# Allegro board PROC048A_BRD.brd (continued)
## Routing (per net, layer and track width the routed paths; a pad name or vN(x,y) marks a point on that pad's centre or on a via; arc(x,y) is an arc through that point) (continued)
AR1243_LVDS_MODE: length 53.7
  TOP w0.14: SW2.3 11.4,72.65 11.54,72.79 v1(12.01,72.79) ; U12.C6 v1(39.4,40.31)
  L03_SIG1 w0.107: v1(12.01,72.79) 13.56,71.24 13.56,68.88 23.59,58.85 33.62,58.85 36.7,55.77 36.7,53.35 36.04,52.68 36.04,43.68 v1(39.4,40.31)
  BOTTOM w0.14: v1(12.01,72.79) 11.51,72.79 11.4,72.68 R175.2
BST1_REGA: length 1.8
  TOP w0.457: U1.15 30.29,81.35 30.7,80.95
BST1_REGB: length 1.8
  TOP w0.457: 55.47,80.95 55.06,81.35 U2.15
BST2_REGA: length 1.7
  TOP w0.457: U1.10 27.05,81.43 26.68,81.07
BST2_REGB: length 1.7
  TOP w0.457: 51.45,81.07 51.81,81.43 U2.10
C_RGMII_RXC: length 6.4
  TOP w0.14: R47.2 55.38,58.3 56.23,57.45 57.88,57.45 59,58.57 60.18,58.57 U6.43
C_RGMII_RXCTL: length 9.6
  TOP w0.14: R66.2 59.02,49.45 59.23,49.66 R64.2 59.78,50.08 60.55,49.32 61.69,49.32 62.54,50.17 R63.2 62.54,51.32 64.13,52.91 64.13,54.12
C_RGMII_RXD0: length 7.5
  TOP w0.14: U6.44 59.14,58.07 58.01,56.94 56.99,56.94 v1(56.36,56.31) 56.1,56.05 55.89,56.05 R48.1
  BOTTOM w0.14: v1(56.36,56.31) 56.36,56.43 56.65,56.73 R185.2 R184.2
C_RGMII_RXD1: length 10.5
  TOP w0.14: U6.45 59.27,57.57 56.36,54.66 56.1,54.66 53.56,52.12 52.8,52.12 52.55,51.86 R60.1
C_RGMII_RXD2: length 12
  TOP w0.14: U6.46 60.1,56.99 59.33,56.99 58.9,56.56 58.9,55.04 58.01,54.15 56.48,54.15 v1(54.32,51.99) 54.07,51.99 53.69,51.61 R61.1
  BOTTOM w0.14: R186.1 R187.2 54.83,51.85 54.69,51.99 v1(54.32,51.99)
C_RGMII_RXD3: length 10.9
  TOP w0.14: U6.47 61.17,56.57 61.31,56.43 61.31,54.78 60.04,53.51 56.61,53.51 54.83,51.74 R62.1
C_RGMII_RXD4: length 10.7
  TOP w0.14: v1(59.09,54.09) 59.48,54.09 60.18,54.8 U6.48
  BOTTOM w0.14: R189.1 R188.2 53.69,52.12 54.2,52.62 57.63,52.62 v1(59.09,54.09)
C_RGMII_RXD6: length 9.5
  TOP w0.14: U6.50 62.63,53.15 62.49,53.01 58.77,53.01 57.75,51.99 57.75,50.72 57.63,50.6 R59.2 R65.1
C_RGMII_RXD7: length 6.3
  TOP w0.14: R55.1 R56.2 60.3,52.25 60.67,52.62 62.71,52.62 63.13,53.05 U6.51
CAPTURE_START: length 51.6
  TOP w0.14: C89.2 R153.2 R151.1 v1(2.63,14.2) ; v1(34.38,28.49) 35.58,28.49 U12.U1
  L08_SIG2 w0.107: v1(34.38,28.49) 33.5,27.61 33.5,24.56 31.97,23.03 31.97,19.86 33.43,18.4 33.43,14.84 32.23,13.64 3.2,13.64 v1(2.63,14.2)
CFG0: length 24.9
  TOP w0.14: U12.U4 v1(37.8,28.31) ; v1(28.29,14.27) S1.7
  L03_SIG1 w0.107: v1(37.8,28.31) 37.38,27.9 37.38,26.56 37.16,26.33 36.8,26.33 36.62,26.16 36.62,25.52 36.29,25.19 36.29,21.13 33.88,18.72 33.88,15.16 31.97,13.25 29.3,13.25 v1(28.29,14.27)
  BOTTOM w0.14: v1(28.29,14.27) R217.2
CFG1: length 24.3
  TOP w0.14: v1(29.56,14.27) S1.6 ; U12.T4 v1(37.8,29.11)
  L03_SIG1 w0.107: v1(29.56,14.27) 30.12,13.71 31.79,13.71 33.37,15.29 33.37,18.59 35.81,21.03 35.81,26.97 35.94,27.1 36.47,27.1 36.59,27.22 36.59,28.8 36.91,29.11 v1(37.8,29.11)
  BOTTOM w0.14: R216.2 v1(29.56,14.27)
CFG2: length 22.5
  TOP w0.14: S1.5 v1(30.83,14.14) ; U12.R4 v1(37.8,29.91)
  L03_SIG1 w0.107: v1(30.83,14.14) 30.83,17.95 32.86,19.99 33.11,19.99 35.02,21.89 35.02,26.97 35.65,27.61 35.65,28.37 36.8,29.51 37.4,29.51 v1(37.8,29.91)
  BOTTOM w0.14: R215.2 v1(30.83,14.14)
CONFIG_VIA_HW: length 57.2
  TOP w0.14: SW2.5 8.86,72.68 9,72.82 v1(9.37,72.82) ; U12.A7 v1(40.2,41.91)
  L03_SIG1 w0.107: v1(9.37,72.82) 11.14,74.6 17.62,74.6 31.72,60.5 36.42,60.5 39.04,57.88 39.04,45.34 38.88,45.18 38.88,43.24 v1(40.2,41.91)
  BOTTOM w0.14: v1(9.37,72.82) 9,72.82 8.86,72.68 R177.2
CONN_SPI_CLK: length 6.6
  TOP w0.14: R92.2 R91.2 26.06,34.59 24.35,34.59 23.3,33.54 J3.9
CONN_SPI_CSN: length 10.4
  TOP w0.14: J3.7 23.04,34.04 23.97,34.97 25.49,34.97 26.13,35.61 26.13,38.4 26.51,38.78 R86.2 R85.2
CONN_SPI_MISO: length 5.1
  TOP w0.14: R96.2 R90.2 13.3,33.32 13.59,33.04 J3.12
CONN_SPI_MOSI: length 8.8
  TOP w0.14: R99.2 28.88,35.55 R101.2 26.38,34.46 26.13,34.21 24.73,34.21 23.56,33.04 J3.11
DATA_TRANS_PROG_LED1: length 83.1
  TOP w0.14: LD1.1 v1(3.02,93.65) ; U12.E6 v1(39.4,38.71)
  L03_SIG1 w0.107: v1(3.02,93.65) 2.51,93.14 2.51,69.39 5.17,66.72 13.3,66.72 23.21,56.82 32.86,56.82 34,55.67 34,43.73 34.89,42.85 35.4,42.85 37.43,40.81 37.84,40.81 38.19,40.46 38.19,39.29 38.37,39.11 39,39.11 v1(39.4,38.71)
DDR3_A0: length 48.7
  TOP w0.14: U12.K18 v1(49.8,34.71) ; U11.K3 v1(76.9,39.68) ; U10.K3 v1(64.29,39.68)
  L08_SIG2 w0.107: v1(49.8,34.71) 49.8,34.97 49.38,35.39 49.38,35.73 49.58,35.93 51.93,35.93 52.8,36.81 52.8,37.86 52.37,38.29 51.26,38.29 51.15,38.4 51.15,38.66 51.26,38.77 53.94,38.77 55.22,40.06 58,40.06 58.39,39.67 58.89,39.67 59.28,40.06 59.76,40.06 59.87,40.17 59.87,41.53 59.99,41.66 60.57,41.66 60.67,41.55 60.67,40.17 60.78,40.06 61.75,40.06 61.86,40.17 61.86,40.77 61.97,40.88 62.18,40.88 62.29,40.77 62.29,40.17 62.39,40.06 63.21,40.06 63.59,39.68 v1(64.29,39.68) 64.74,39.68 65.13,40.06 67.41,40.06 67.91,40.56 67.91,41.07 68.5,41.66 73.62,41.66 75.6,39.68 v1(76.9,39.68)
  BOTTOM w0.14: RA6.6 76.67,44.07 75.9,43.3 75.9,40.67 v1(76.9,39.68)
DDR3_A1: length 47.6
  TOP w0.14: U11.L7 v1(72.9,40.48) ; U10.L7 v1(61.09,40.48) ; U12.G20 v1(53.17,36.71)
  L03_SIG1 w0.107: v1(53.17,36.71) 52.87,36.71 52.77,36.82 52.77,36.97 53.94,38.15 53.94,38.79 53.84,38.89 53.03,38.89 52.93,39 52.93,39.21 53.03,39.32 53.84,39.32 53.94,39.43 53.94,40.31 54.07,40.43 55.72,40.43 55.97,40.69 55.97,42.85 56.48,43.35 56.48,45.13 57.22,45.87 59.81,45.87 59.91,45.77 59.91,43.86 59.66,43.61 59.02,43.61 58.64,43.23 58.64,41.07 58.85,40.86 60.49,40.86 60.53,40.81 60.75,40.81 v1(61.09,40.48) 62.51,40.48 63.73,41.7 66.89,41.7 67.39,42.2 69.29,42.2 69.4,42.09 69.4,40.72 69.69,40.43 70.71,40.43 71.13,40.86 72.52,40.86 v1(72.9,40.48)
  BOTTOM w0.14: RA7.7 73.5,43.4 73.78,43.13 73.78,41.04 73.22,40.48 v1(72.9,40.48)
DDR3_A2: length 47.8
  TOP w0.14: v1(52.01,37.11) 50.6,37.11 U12.G19 ; U11.L3 v1(76.9,40.48) ; U10.L3 v1(64.29,40.48)
  L08_SIG2 w0.107: v1(52.01,37.11) 49.54,37.11 48.99,37.66 48.99,37.99 49.33,38.33 50.15,38.33 50.26,38.44 50.26,39.26 50.42,39.42 53.51,39.42 54.07,39.98 54.07,40.81 54.26,41 55.54,41 55.83,40.7 58.02,40.7 58.64,41.32 58.64,42.34 59.28,42.97 61.82,42.97 61.94,42.85 61.94,42.59 62.07,42.46 62.35,42.46 62.45,42.57 62.45,42.87 62.56,42.97 62.87,42.97 63.02,42.82 63.02,41.18 63.72,40.48 v1(64.29,40.48) 64.6,40.48 65.02,40.9 66.05,40.9 67.93,42.78 74,42.78 76.31,40.48 v1(76.9,40.48)
  BOTTOM w0.14: v1(76.9,40.48) 76.32,41.06 76.32,43.13 77.17,43.98 RA6.5
DDR3_A3: length 47.5
  TOP w0.14: U11.K2 v1(77.7,39.68) ; U12.J18 v1(49.8,35.51) ; U10.K2 v1(65.89,39.68)
  L08_SIG2 w0.107: v1(77.7,39.68) 77.32,39.3 75.53,39.3 73.96,40.86 70.96,40.86 70.5,41.32 68.8,41.32 68.42,40.94 68.42,39.67 68.04,39.29 66.52,39.29 66.13,39.68 v1(65.89,39.68) 65.25,39.68 64.83,39.26 61.66,39.26 61.31,38.91 60.04,38.91 59.66,39.29 58.2,39.29 57.82,39.67 56.61,39.67 56.48,39.54 56.48,38.53 56.36,38.4 56.1,38.4 55.97,38.53 55.97,39.54 55.85,39.67 55.34,39.67 55.09,39.42 55.09,38.65 54.83,38.4 53.69,38.4 53.56,38.27 53.56,36.5 53.33,36.27 52.95,36.27 52.2,35.51 51.73,35.51 51.62,35.41 51.62,34.32 51.52,34.21 51.3,34.21 51.2,34.32 51.2,35.41 51.09,35.51 50.88,35.51 50.77,35.41 50.77,34.32 50.66,34.21 50.45,34.21 50.34,34.32 50.34,35.41 50.24,35.51 v1(49.8,35.51)
  BOTTOM w0.14: v1(77.7,39.68) 80.99,39.68 81.16,39.5 81.99,39.5 RA9.8
DDR3_A4: length 48
  TOP w0.14: U10.L8 v1(60.29,40.48) ; U12.J19 50.6,35.51 v1(53.69,35.51) ; U11.L8 v1(72.1,40.48)
  L03_SIG1 w0.107: v1(72.1,40.48) 72.05,40.43 71.85,40.43 71.51,40.1 69.52,40.1 69.06,40.56 69.06,41.7 68.93,41.83 67.79,41.83 67.66,41.7 67.66,41.27 67.25,40.86 63.51,40.86 62.75,40.1 60.93,40.1 60.55,40.48 v1(60.29,40.48) 60.05,40.48 59.63,40.06 58.64,40.06 58.26,40.43 58.26,43.86 58.39,43.99 59.4,43.99 59.53,44.12 59.53,45.39 59.4,45.51 57.37,45.51 56.86,45 56.86,43.1 56.36,42.59 56.36,41.58 56.86,41.07 56.86,40.81 56.1,40.05 54.45,40.05 54.32,39.92 54.32,38.02 53.69,37.38 v1(53.69,35.51)
  BOTTOM w0.14: v1(72.1,40.48) 72.49,40.88 73.06,40.88 73.36,41.18 73.36,42.95 73,43.31 RA7.8
DDR3_A5: length 48.6
  TOP w0.14: U10.L2 v1(65.89,40.48) ; U11.L2 v1(77.7,40.48) ; U12.J16 v1(48.2,35.51)
  L08_SIG2 w0.107: v1(77.7,40.48) 77.32,40.1 75.74,40.1 75.02,40.81 75.02,41.31 73.87,42.46 68.06,42.46 67.66,42.06 67.66,41.29 67.23,40.86 66.46,40.86 66.26,40.66 66.26,40.56 66.18,40.48 v1(65.89,40.48) 65.09,40.48 64.71,40.1 63.65,40.1 62.51,41.23 62.51,41.39 61.31,42.59 59.46,42.59 59.02,42.15 59.02,40.94 58.46,40.38 55.03,40.38 53.75,39.1 50.96,39.1 50.83,38.98 50.83,37.64 50.97,37.51 52.29,37.51 52.42,37.38 52.42,36.88 52.24,36.69 48.84,36.69 48.2,36.05 v1(48.2,35.51)
  BOTTOM w0.14: v1(77.7,40.48) 78.44,41.22 78.71,41.22 79.84,42.36 RA5.5
DDR3_A6: length 47.1
  TOP w0.14: v1(53.05,38.15) 53.69,38.15 53.82,38.27 53.82,38.9 53.68,39.04 52.42,39.04 51.69,38.31 51.01,38.31 U12.E20 ; U10.M8 v1(60.29,41.28) ; U11.M8 v1(72.1,41.28)
  L03_SIG1 w0.107: v1(72.1,41.28) 72.05,41.32 71.86,41.32 71.53,41.66 71.04,41.66 70.71,41.32 69.94,41.32 69.82,41.45 69.82,42.34 69.64,42.52 63.14,42.52 62.83,42.21 62.83,41.32 62.41,40.9 61.48,40.9 61.24,41.13 60.66,41.13 60.52,41.28 v1(60.29,41.28) 60.03,41.28 59.64,41.66 59.13,41.66 59.02,41.77 59.02,42.85 59.28,43.1 59.91,43.1 60.29,43.48 60.29,43.86 60.29,46.07 60.17,46.2 56.91,46.2 56.1,45.39 56.1,43.73 55.59,43.23 55.59,41.19 55.21,40.81 53.05,40.81 52.55,40.31 52.55,37.62 52.65,37.52 52.8,37.52 53.05,37.77 v1(53.05,38.15)
  BOTTOM w0.14: v1(72.1,41.28) 71.69,41.68 71.69,42.24 70.34,43.6 RA8.8
DDR3_A7: length 47.8
  TOP w0.14: U12.K17 v1(49,34.71) ; U10.M2 v1(65.89,41.28) ; U11.M2 v1(77.7,41.28)
  L08_SIG2 w0.107: v1(77.7,41.28) 77.7,41 77.51,40.81 77.18,40.81 77.14,40.86 76.37,40.86 75.91,41.32 75.91,41.7 74.52,43.1 67.02,43.1 66.26,42.34 66.26,41.65 v1(65.89,41.28) 64.95,41.28 64.57,40.9 63.76,40.9 63.34,41.31 63.34,42.95 63,43.29 58.96,43.29 58.26,42.59 58.26,41.7 57.68,41.13 55.92,41.13 55.72,41.32 54.07,41.32 53.69,40.94 53.69,40.05 53.43,39.8 50.35,39.8 48.48,37.93 48.48,36.79 47.82,36.12 47.82,35.36 48.04,35.13 48.35,35.13 48.77,34.71 v1(49,34.71)
  BOTTOM w0.14: RA5.6 79.34,42.36 78.56,41.58 78,41.58 v1(77.7,41.28)
DDR3_A8: length 46.2
  TOP w0.14: U11.N8 v1(72.1,42.08) ; U10.N8 v1(60.29,42.08) ; U12.J20 v1(52.8,35.11)
  L03_SIG1 w0.107: v1(72.1,42.08) 72.74,42.72 72.74,43.13 72.63,43.23 62.84,43.23 61.43,41.82 60.93,41.82 60.67,42.08 v1(60.29,42.08) 60.29,42.46 61.05,43.23 61.05,46.45 60.67,46.84 55.8,46.84 55.28,46.32 55.28,43.98 52.88,41.58 52.87,41.58 51.47,40.17 51.47,36.18 51.78,35.86 53.18,35.86 53.31,35.73 53.31,35.22 53.2,35.11 v1(52.8,35.11)
  BOTTOM w0.14: v1(72.1,42.08) 72.1,42.44 70.84,43.7 RA8.7
DDR3_A9: length 47.5
  TOP w0.14: U10.M3 v1(64.29,41.28) ; U11.M3 v1(76.9,41.28) ; U12.D20 51.35,39.11 52.93,40.69 52.93,41.71 53.17,41.96 53.69,41.96 53.88,41.77 53.88,40.43 53.76,40.31 v1(53.31,40.31)
  L08_SIG2 w0.107: v1(53.31,40.31) 52.27,40.31 52.16,40.41 52.16,41.22 52.27,41.32 53.46,41.32 53.79,41.64 55.03,41.64 55.16,41.78 55.16,42.87 55.27,42.97 55.87,42.97 55.97,42.87 55.97,41.58 56.1,41.45 57.5,41.45 57.88,41.83 57.88,43.61 58.19,43.92 62.83,43.92 63.66,43.09 63.66,41.45 63.83,41.28 v1(64.29,41.28) 64.61,41.6 65.2,41.6 65.72,42.12 65.72,42.3 66.9,43.48 74.7,43.48 v1(76.9,41.28)
  BOTTOM w0.14: v1(76.9,41.28) 77.3,41.68 77.3,42.33 78.84,43.87 RA5.7
DDR3_A10: length 51.1
  TOP w0.14: U12.K19 50.6,34.71 53.56,34.71 54.2,35.35 54.2,36.36 54.34,36.5 55.09,36.5 55.34,36.24 55.34,34.72 55.12,34.5 54.79,34.5 v1(54.45,34.84) ; U11.H7 v1(72.9,38.08) ; U10.H7 v1(61.89,37.28)
  L03_SIG1 w0.107: v1(54.45,34.84) 54.45,35.61 54.58,35.73 54.78,35.73 54.96,35.55 54.96,34.02 55.07,33.91 55.23,33.91 55.34,34.02 55.34,35.25 55.45,35.35 56.25,35.35 56.36,35.25 56.36,34.32 56.46,34.21 57.75,34.21 58.51,34.97 58.51,37.51 58.7,37.7 60.49,37.7 60.8,37.38 61.18,37.38 61.56,37.77 61.56,38.29 61.67,38.4 62.35,38.4 62.45,38.29 62.45,37.84 v1(61.89,37.28) 61.91,37.26 62.83,37.26 62.96,37.38 62.96,37.79 63.07,37.89 63.36,37.89 63.47,37.79 63.47,37.49 63.57,37.38 64.48,37.38 64.8,37.7 69.9,37.7 70.01,37.59 70.01,37.11 70.12,37 70.33,37 70.44,37.11 70.44,37.59 70.54,37.7 71.28,37.7 71.47,37.51 71.47,37.26 71.85,36.88 72.36,36.88 72.52,37.04 72.52,37.7 v1(72.9,38.08)
  BOTTOM w0.14: v1(72.9,38.08) 73.27,38.45 73.49,38.45 73.57,38.53 74.14,38.53 75.06,39.46 75.06,43.66 75.67,44.27 RA6.8
DDR3_A11: length 47.1
  TOP w0.14: v1(52.01,37.91) 50.6,37.91 U12.F19 ; U10.M7 61.89,41.28 v1(61.98,41.28) ; U11.M7 v1(72.9,41.28)
  L03_SIG1 w0.107: v1(52.01,37.91) 52.01,37.93 51.79,38.14 51.79,38.53 52.23,38.97 52.23,39.36 51.79,39.79 51.79,40.04 52.94,41.19 54.09,41.19 54.2,41.3 54.2,42.23 54.31,42.34 54.52,42.34 54.63,42.23 54.63,41.3 54.73,41.19 54.96,41.19 55.21,41.45 55.21,43.35 55.72,43.86 55.72,45.51 56.73,46.52 60.43,46.52 60.66,46.29 60.66,43.34 59.87,42.55 59.87,41.96 60.13,41.7 60.55,41.7 60.8,41.45 61.8,41.45 v1(61.98,41.28) 62.43,41.73 62.43,42.31 62.95,42.84 63.01,42.84 63.01,42.84 70.09,42.84 70.2,42.73 70.2,42.11 70.33,41.98 70.73,41.98 70.83,42.09 70.83,42.74 70.94,42.85 71.61,42.85 71.72,42.74 71.72,41.92 71.98,41.66 72.52,41.66 v1(72.9,41.28)
  BOTTOM w0.14: RA8.6 71.34,43.79 72.49,42.63 72.49,41.68 v1(72.9,41.28)
DDR3_A12: length 48.9
  TOP w0.14: U12.F20 51.01,37.51 54.45,37.51 v1(54.45,37.51) ; U10.K7 v1(61.09,39.68) ; U11.K7 v1(72.9,39.68)
  L03_SIG1 w0.107: v1(54.45,37.51) 54.45,36.67 54.56,36.56 54.85,36.56 54.96,36.67 54.96,39.54 55.14,39.73 56.29,39.73 57.24,40.69 57.24,41.19 56.74,41.7 56.74,42.34 57.19,42.79 57.19,44.87 57.45,45.13 59.1,45.13 59.21,45.03 59.21,44.48 59.1,44.37 58.01,44.37 57.88,44.24 57.88,40.31 58.89,39.3 59.64,39.3 59.91,39.56 59.91,39.84 60.13,40.06 60.49,40.06 60.77,39.77 60.99,39.77 v1(61.09,39.68) 63.35,39.68 63.73,40.06 66.9,40.06 67.28,40.43 67.68,40.43 67.79,40.54 67.79,40.94 67.91,41.07 68.55,41.07 68.67,40.94 68.67,40.18 69.56,39.3 71.46,39.3 71.68,39.52 71.68,39.8 71.94,40.06 72.52,40.06 v1(72.9,39.68)
  BOTTOM w0.14: v1(72.9,39.68) 73.42,39.68 74.5,40.77 RA7.5
DDR3_A13: length 46.3
  TOP w0.14: U12.L19 50.6,33.91 55.17,33.91 55.34,34.08 57.75,34.08 58.17,34.5 58.17,37.55 57.24,38.47 v1(57.24,41.96) ; U11.N3 v1(76.9,42.08) ; U10.N3 v1(64.29,42.08)
  L08_SIG2 w0.107: v1(57.24,41.96) 56.74,42.46 56.74,43.86 57.12,44.24 62.96,44.24 63.98,43.22 63.98,42.38 v1(64.29,42.08) 64.71,42.5 64.71,43.32 65.25,43.86 75.11,43.86 v1(76.9,42.08)
  BOTTOM w0.14: v1(76.9,42.08) 76.9,42.57 78.34,44.01 RA5.8
DDR3_A14: length 46.3
  TOP w0.14: U11.N7 v1(72.9,42.08) ; U12.K16 v1(48.2,34.71) ; v1(61.09,42.2) 61.09,42.08 U10.N7
  L03_SIG1 w0.107: v1(48.2,34.71) 48.2,34.97 48.58,35.36 48.58,36.47 48.85,36.73 49.23,36.73 49.51,37.01 50.78,37.01 51.11,37.35 51.11,40.27 54.96,44.12 54.96,46.46 55.67,47.16 60.8,47.16 61.44,46.53 61.44,43.1 61.09,42.75 v1(61.09,42.2) 61.36,42.2 62.71,43.55 63.41,43.55 63.42,43.56 73.04,43.56 73.5,43.1 73.5,42.68 v1(72.9,42.08)
  BOTTOM w0.14: v1(72.9,42.08) 72.88,42.09 72.88,42.26 72.91,42.29 72.91,42.81 71.84,43.88 RA8.5
DDR3_A15: length 51.5
  TOP w0.14: U10.J7 v1(61.89,38.88) ; U12.J17 v1(49,35.51) ; U11.J7 v1(73.7,38.08)
  L03_SIG1 w0.107: v1(73.7,38.08) 73.75,38.13 73.75,38.37 73.65,38.47 71.92,38.47 71.47,38.02 68.15,38.02 68.04,38.13 68.04,38.87 67.88,39.04 67.4,39.04 67.28,38.91 67.28,38.13 67.17,38.02 66.52,38.02 66.07,38.47 64.8,38.47 64.39,38.88 v1(61.89,38.88) 60.52,38.88 59.81,38.18 58.29,38.18 58.13,38.02 58.13,35.1 58.01,34.97 57.63,34.97 57.5,35.1 57.5,39.31 57.39,39.42 56.99,39.42 56.48,38.91 56.48,36.24 55.97,35.73 55.47,35.73 55.01,36.19 54.15,36.19 54.07,36.11 54.07,35.05 53.73,34.72 52.29,34.72 51.15,35.86 51.15,36.5 50.95,36.69 49.64,36.69 49.38,36.44 49.38,36.13 49,35.75 v1(49,35.51)
  BOTTOM w0.14: v1(73.7,38.08) 74.94,38.08 75.48,38.62 75.48,43.47 76.17,44.16 RA6.7
DDR3_BA0: length 48.3
  TOP w0.14: U11.J2 v1(77.7,38.88) ; U10.J2 v1(65.89,38.88) ; v1(56.99,37.64) 56.99,38.13 56.85,38.27 55.35,38.27 55.08,38.54 55.08,39.66 55.22,39.8 56.18,39.8 56.32,39.94 56.32,40.89 56.18,41.03 55.57,41.03 55.43,41.17 55.43,41.45 55.57,41.59 56.18,41.59 56.32,41.73 56.32,43.01 56.1,43.23 55.59,43.23 55.47,43.1 55.47,42.59 55.21,42.34 53.05,42.34 52.53,41.81 52.53,40.85 51.2,39.52 50.6,39.52 U12.D19
  L08_SIG2 w0.107: v1(77.7,38.88) 77.28,38.46 75.02,38.46 74.7,38.78 72.96,38.78 72.48,39.26 70.74,39.26 70.58,39.42 70.58,39.95 70.47,40.05 69.29,40.05 69.18,39.95 69.18,39.16 68.2,38.18 66.52,38.18 65.89,38.81 v1(65.89,38.88) 65.85,38.88 65.47,38.5 62.8,38.5 61.96,37.66 57.65,37.66 57.63,37.64 v1(56.99,37.64)
  BOTTOM w0.14: v1(77.7,38.88) 78.87,38.88 79.47,38.27 80.87,38.27 81.1,38.5 81.1,38.5 81.63,39.03 RA9.7
DDR3_BA1: length 49.7
  TOP w0.14: v1(55.53,38.97) 56.17,38.97 56.74,39.54 56.74,43.61 56.48,43.86 55.18,43.86 55.04,43.72 55.04,42.9 54.9,42.76 54.62,42.76 54.48,42.9 54.48,43.72 54.35,43.86 54.07,43.86 53.93,43.72 53.93,42.9 53.79,42.76 52.84,42.76 52.16,42.08 52.16,41.07 U12.C20 ; U11.K8 v1(72.1,39.68) ; U10.K8 v1(60.29,39.68)
  L03_SIG1 w0.107: v1(55.53,38.97) 55.53,36.35 55.64,36.24 55.97,36.24 56.1,36.37 56.1,39.04 56.81,39.74 57.94,39.74 59.18,38.5 59.64,38.5 60.29,39.14 v1(60.29,39.68) 60.67,39.3 67.16,39.3 67.4,39.54 67.4,39.95 67.51,40.05 68.29,40.05 68.42,39.93 68.42,38.91 68.83,38.5 71.46,38.5 71.72,38.76 71.72,39.04 72.1,39.42 v1(72.1,39.68)
  BOTTOM w0.14: RA7.6 74,43.49 74.15,43.35 74.15,40.91 73.31,40.08 72.49,40.08 v1(72.1,39.68)
DDR3_BA2: length 49
  TOP w0.14: U10.J3 v1(65.09,38.88) ; U12.H17 v1(49,36.31) ; U11.J3 v1(76.9,38.88)
  L08_SIG2 w0.107: v1(76.9,38.88) 75.44,38.88 74.26,40.06 71.08,40.06 70.45,40.69 69.18,40.69 68.8,40.31 68.8,39.42 67.88,38.5 66.66,38.5 66.39,38.76 66.39,38.96 66.09,39.26 65.47,39.26 v1(65.09,38.88) 62.55,38.88 62.13,38.46 60.1,38.46 59.71,38.07 57.63,38.07 57.5,38.2 57.5,39.29 57.44,39.35 57.03,39.35 56.93,39.24 56.93,38.18 56.74,37.99 54.22,37.99 53.94,37.72 53.94,36.32 53.57,35.95 53.09,35.95 52.42,35.27 52.42,33.83 52.29,33.7 48.48,33.7 48.37,33.82 48.37,34.09 48.48,34.21 49.24,34.21 49.42,34.39 49.42,34.83 49.12,35.13 48.84,35.13 48.62,35.36 48.62,35.93 v1(49,36.31)
  BOTTOM w0.14: RA9.6 81.72,38.53 81.04,37.85 79.25,37.85 78.63,38.48 77.3,38.48 v1(76.9,38.88)
DDR3_CASN: length 48.7
  TOP w0.14: U11.G3 v1(76.9,37.28) ; U10.G3 v1(65.09,37.28) ; U12.E19 50.6,38.72 51.46,38.72 52.16,39.42 53.43,39.42 54.32,40.31 54.32,41.56 54.46,41.7 54.83,41.7 54.96,41.58 54.96,40.18 54.45,39.67 54.45,38.36 55.62,37.19 57.57,37.19 57.75,37 57.75,35.86 57.63,35.73 v1(56.61,35.73)
  L08_SIG2 w0.107: v1(76.9,37.28) 76.9,36.98 76.79,36.88 71.47,36.88 71.34,37 71.34,37.53 71.24,37.64 70.56,37.64 70.45,37.53 70.45,36.62 70.33,36.5 68.15,36.5 68.04,36.6 68.04,37 67.91,37.13 66.52,37.13 66.26,36.88 65.49,36.88 v1(65.09,37.28) 64.63,37.28 63.21,35.86 63.21,35.61 62.07,34.46 59.02,34.46 58.77,34.21 57.45,34.21 56.61,35.05 v1(56.61,35.73)
  BOTTOM w0.14: RA10.7 81.34,36.36 81.21,36.5 77.82,36.5 77.31,37 77.18,37 76.91,37.28 v1(76.9,37.28)
DDR3_CK: length 45.3
  TOP w0.102: U11.F7 v1(72.9,35.68) ; U12.U18 v1(49.8,28.31) ; U10.F7 v1(61.09,35.68)
  L03_SIG1 w0.089: v1(61.09,35.68) 61.36,35.95 62.92,35.95 63.21,36.24 65.05,36.24 65.48,35.81 68.3,35.81 68.39,35.72 68.39,35.1 68.65,34.84 69.07,34.84 69.33,35.1 69.33,35.72 69.42,35.81 71.45,35.81 71.84,36.2 72.61,36.2 72.73,36.33 72.81,36.33 72.9,36.24 v1(72.9,35.68)
  BOTTOM w0.102: v1(61.09,35.68) 61.09,35.33 61.19,35.23 61.44,35.23 61.56,35.35 61.56,36.1 61.66,36.2 62.48,36.2 62.93,35.75 62.93,30.64 60.79,28.49 58.26,28.49 57.75,29 57.75,30.77 57.49,31.03 56.49,31.03 56.22,30.77 56.22,29.1 56.12,29 52.66,29 51.87,28.22 50.39,28.22 50.26,28.34 50.26,28.58 50.16,28.68 49.9,28.68 49.8,28.58 v1(49.8,28.31) ; R210.1 73.62,36.34 73,36.34 72.9,36.24 v1(72.9,35.68)
DDR3_CKE: length 52.7
  TOP w0.14: U12.L20 51.07,33.45 52.03,33.45 52.17,33.31 52.17,32.32 52.31,32.18 52.59,32.18 52.73,32.32 52.73,33.28 52.87,33.42 53.15,33.42 53.29,33.28 53.29,32.32 53.43,32.18 53.71,32.18 53.85,32.32 53.85,33.28 53.99,33.42 54.48,33.42 54.65,33.25 54.65,31.95 54.79,31.81 55.07,31.81 55.21,31.95 55.21,32.93 55.35,33.07 56.99,33.07 57.24,32.81 58.76,32.81 58.9,32.95 58.9,33.44 58.76,33.57 v1(55.72,33.57) ; v1(70.96,36.62) 71.21,36.88 U11.G9 ; U10.G9 v1(59.49,37.28)
  L03_SIG1 w0.107: v1(55.72,33.57) 55.97,33.83 57.88,33.83 58.9,34.84 58.9,36.01 59,36.11 60.06,36.11 60.17,36.22 60.17,36.39 60.06,36.5 59.11,36.5 58.9,36.71 58.9,37.17 59,37.28 v1(59.49,37.28) 59.87,36.9 66.15,36.9 66.52,37.26 67.53,37.26 67.66,37.13 67.66,36.62 67.79,36.5 68.06,36.5 68.17,36.6 68.17,37.02 68.27,37.13 68.57,37.13 68.67,37.02 68.67,36.6 68.78,36.5 69.06,36.5 69.18,36.62 69.18,37 69.31,37.13 69.56,37.13 69.69,37 69.69,36.75 69.82,36.62 v1(70.96,36.62)
  BOTTOM w0.14: v1(70.96,36.62) 69.82,36.62 69.18,37.26 R191.1
DDR3_CKN: length 45.4
  TOP w0.102: U10.G7 v1(61.09,36.48) ; U12.U17 v1(49,28.31) ; U11.G7 v1(72.9,37.28)
  L03_SIG1 w0.089: v1(72.9,37.28) 72.9,36.71 72.81,36.62 72.61,36.62 72.48,36.5 71.72,36.5 71.33,36.11 69.3,36.11 69.04,35.85 69.04,35.23 68.95,35.14 68.77,35.14 68.68,35.23 68.68,35.85 68.42,36.11 65.6,36.11 65.17,36.53 63.09,36.53 62.8,36.24 61.32,36.24 v1(61.09,36.48)
  BOTTOM w0.102: v1(72.9,37.28) 72.9,36.72 73,36.62 73.58,36.62 R209.1 ; v1(61.09,36.48) 62.6,36.48 63.21,35.86 63.21,30.53 60.9,28.22 58.15,28.22 57.47,28.89 57.47,30.65 57.37,30.76 56.6,30.76 56.5,30.65 56.5,28.99 56.23,28.72 52.77,28.72 51.99,27.94 49.38,27.94 v1(49,28.31)
DDR3_CSN: length 48.2
  TOP w0.14: U12.T17 v1(49,29.11) ; U10.H2 v1(65.89,38.08) ; U11.H2 v1(77.7,38.08)
  L08_SIG2 w0.107: v1(77.7,38.08) 77.32,37.7 75.28,37.7 74.52,38.46 70.14,38.46 70.04,38.57 70.04,39.44 69.93,39.54 69.72,39.54 69.61,39.44 69.61,38.57 69.5,38.46 69.04,38.46 68.42,37.84 66.41,37.84 66.17,38.08 v1(65.89,38.08) 65.82,38.15 62.96,38.15 62.45,37.64 62.45,36.24 62.32,36.11 61.94,36.11 61.82,36.24 61.82,36.75 61.67,36.9 56.59,36.9 56.48,37 56.48,37.53 56.38,37.64 55.95,37.64 55.85,37.53 55.85,36.86 55.74,36.75 55.21,36.75 54.45,35.99 54.45,35.61 53.82,34.97 53.43,34.97 52.8,34.34 52.8,33.19 52.3,32.7 48.84,32.7 48.62,32.47 48.62,29.5 v1(49,29.11)
  BOTTOM w0.14: RA9.5 81.81,38.03 81.22,37.44 81.17,37.44 81.16,37.42 78.35,37.42 v1(77.7,38.08)
DDR3_DM0: length 36.6
  TOP w0.14: U12.U19 50.6,28.31 52.22,28.31 52.42,28.11 52.42,26.08 52.67,25.83 54.2,25.83 54.58,26.21 v1(54.58,28.24) ; U11.B7 v1(72.9,32.48)
  L08_SIG2 w0.107: v1(54.58,28.24) 55.09,28.75 57.88,28.75 58.39,29.26 58.88,29.26 58.99,29.15 58.99,28.24 59.1,28.14 59.31,28.14 59.42,28.24 59.42,29.15 59.52,29.26 59.74,29.26 59.84,29.15 59.84,28.24 59.95,28.14 60.16,28.14 60.27,28.24 60.27,29.15 60.38,29.26 64.48,29.26 64.86,28.88 66.8,28.88 67.05,28.62 67.79,28.62 68.17,29 68.17,30.53 68.42,30.78 71.47,30.78 71.68,30.99 71.68,31.88 71.89,32.1 72.22,32.1 72.62,31.69 72.89,31.69 73.21,32.01 73.21,32.16 v1(72.9,32.48)
DDR3_DM1: length 30.8
  TOP w0.14: v1(62.06,28.57) 62.06,32.63 61.82,32.88 U10.B7 ; U12.R17 v1(49,29.91)
  L03_SIG1 w0.107: v1(62.06,28.57) 62.32,28.31 62.59,28.31 62.7,28.21 62.7,27.46 62.81,27.35 63.02,27.35 63.13,27.46 63.13,28.21 63.23,28.31 63.45,28.31 63.55,28.21 63.55,27.46 63.66,27.35 63.87,27.35 63.98,27.46 63.98,28.21 64.09,28.31 64.41,28.31 64.61,28.11 64.61,26.97 64.43,26.79 53.49,26.79 53.18,27.1 49.68,27.1 49.38,27.39 49.38,29.53 v1(49,29.91)
DDR3_DQ0: length 36.7
  TOP w0.14: U11.B3 75.91,32.29 v1(75.91,31.67) ; U12.N20 51.53,31.91 52.29,31.16 55.18,31.16 56.36,29.98 v1(56.36,25.83)
  L08_SIG2 w0.107: v1(56.36,25.83) 56.74,26.21 64.23,26.21 64.7,26.68 71.98,26.68 75.44,30.15 76.8,30.15 77.18,30.52 77.18,31.3 76.8,31.67 v1(75.91,31.67)
DDR3_DQ1: length 36.2
  TOP w0.14: U12.P19 v1(50.6,30.71) ; U11.C7 v1(72.9,33.28)
  L08_SIG2 w0.107: v1(50.6,30.71) 50.98,30.33 53.77,30.33 54.41,30.97 61.36,30.97 61.46,30.86 61.46,30.07 61.57,29.96 61.78,29.96 61.89,30.07 61.89,30.67 62,30.78 62.21,30.78 62.32,30.67 62.32,30.07 62.42,29.96 62.64,29.96 62.74,30.07 62.74,30.67 62.85,30.78 63.06,30.78 63.17,30.67 63.17,30.07 63.28,29.96 63.49,29.96 63.6,30.07 63.6,30.86 63.7,30.97 64.77,30.97 65.22,30.53 67.02,30.53 68.04,31.54 70.07,31.54 70.33,31.8 70.33,33.59 70.43,33.7 72.61,33.7 72.74,33.83 73.7,33.83 74.48,34.61 74.73,34.61 74.83,34.5 74.83,33.64 74.47,33.28 v1(72.9,33.28)
DDR3_DQ2: length 36.7
  TOP w0.14: v1(55.85,27.22) 55.85,26.48 55.71,26.34 55.23,26.34 55.09,26.48 55.09,28.88 55.47,29.26 55.47,30.27 55.09,30.65 52.14,30.65 51.28,31.51 50.6,31.51 U12.N19 ; U11.C2 v1(77.7,33.28)
  L08_SIG2 w0.107: v1(55.85,27.22) 56.99,27.22 57.32,26.89 64,26.89 64.44,27.33 70.58,27.33 75.82,32.57 76.99,32.57 v1(77.7,33.28)
DDR3_DQ3: length 36.3
  TOP w0.14: U12.R20 52,30.31 52.14,30.17 52.14,29.56 52.28,29.42 52.56,29.42 52.7,29.56 52.7,30.1 52.84,30.23 54.82,30.23 54.96,30.1 v1(54.96,29.76) ; U11.C8 v1(72.1,33.28)
  L08_SIG2 w0.107: v1(72.1,33.28) 71.72,32.9 70.94,32.9 70.83,32.79 70.83,31.42 70.58,31.16 68.17,31.16 67.79,30.78 67.79,30.02 67.28,29.51 65.25,29.51 65.12,29.64 58.13,29.64 57.75,29.26 57.22,29.26 57.12,29.36 57.12,30.35 57.01,30.46 56.8,30.46 56.69,30.35 56.69,29.36 56.58,29.26 56.37,29.26 56.26,29.36 56.26,30.35 56.16,30.46 55.94,30.46 55.84,30.35 55.84,29.36 55.73,29.26 55.09,29.26 54.54,28.71 53.03,28.71 52.93,28.81 52.93,29.91 53.03,30.01 54.72,30.01 54.96,29.77 v1(54.96,29.76)
DDR3_DQ4: length 36.8
  TOP w0.14: v1(53.41,28.33) 53.39,28.33 52.93,27.86 52.93,26.59 53.05,26.46 53.82,26.46 54.07,26.72 54.07,28.75 53.88,28.94 52.61,28.94 52.38,28.71 U12.U20 ; v1(75.53,34.84) 76.07,34.84 U11.E3
  L08_SIG2 w0.107: v1(53.41,28.33) 54.01,27.73 54.77,27.73 55.38,28.34 57.53,28.34 58.05,27.81 62.03,27.81 62.46,28.25 68.29,28.25 68.67,28.63 68.67,29.89 69.06,30.27 72.04,30.27 72.74,30.97 72.74,30.97 75.15,33.38 75.15,34.46 v1(75.53,34.84)
DDR3_DQ5: length 36.8
  TOP w0.14: U12.P18 v1(49.8,30.71) ; U11.E8 v1(72.1,34.88)
  L08_SIG2 w0.107: v1(72.1,34.88) 71.62,35.35 68.52,35.35 68.32,35.15 68.32,32.92 68.21,32.81 68,32.81 67.89,32.92 67.89,35.12 67.78,35.23 67.4,35.23 67.28,35.1 67.28,32.48 66.9,32.1 64.63,32.1 64.53,32.2 64.53,33.27 64.42,33.37 64.21,33.37 64.1,33.27 64.1,32.2 63.99,32.1 63.78,32.1 63.67,32.2 63.67,33.27 63.56,33.37 63.35,33.37 63.24,33.27 63.24,31.95 62.96,31.67 61.31,31.67 60.88,32.1 58.69,32.1 58.26,31.67 53.94,31.67 53.56,31.29 50.38,31.29 v1(49.8,30.71)
DDR3_DQ6: length 36.8
  TOP w0.14: U11.D2 v1(77.7,34.08) ; U12.U16 v1(48.2,28.31)
  L08_SIG2 w0.107: v1(77.7,34.08) 78.08,33.7 78.08,32.3 77.83,32.06 75.76,32.06 74.77,31.07 74.77,30.4 71.38,27 64.57,27 64.1,26.53 52.48,26.53 51.91,27.1 51.91,27.61 51.58,27.93 48.58,27.93 v1(48.2,28.31)
DDR3_DQ7: length 36.6
  TOP w0.14: U12.P20 v1(51.4,30.71) ; U11.E7 v1(72.9,34.88)
  L08_SIG2 w0.107: v1(72.9,34.88) 73.75,35.73 75.17,35.73 75.28,35.63 75.28,35.23 75.02,34.97 74.39,34.97 73.63,34.21 72.73,34.21 72.48,34.46 71.09,34.46 70.71,34.84 69.97,34.84 69.86,34.74 69.86,32.03 69.76,31.92 69.51,31.92 69.44,32 69.44,33.79 69.33,33.9 69.04,33.9 68.93,33.79 68.93,32.05 68.8,31.92 68.42,31.92 68.04,32.3 67.66,32.3 67.53,32.18 67.53,31.54 67.28,31.29 54.2,31.29 53.62,30.71 v1(51.4,30.71)
DDR3_DQ8: length 30.9
  TOP w0.14: U12.M19 v1(50.6,32.31) ; U10.B3 v1(65.09,32.48)
  L03_SIG1 w0.107: v1(65.09,32.48) 65.09,34.01 64.95,34.14 64.72,34.14 64.61,34.04 64.61,32.21 65.88,30.94 65.88,29.64 65.75,29.51 64.86,29.51 64.74,29.64 64.74,31.18 64.63,31.29 64.25,31.29 64.1,31.15 64.1,30 64,29.89 61.69,29.89 60.9,29.1 54.6,29.1 54.45,29.26 54.45,30.02 54.32,30.15 53.53,30.15 53.43,30.04 53.43,29.16 53.32,29.05 53.11,29.05 53,29.16 53,30.04 52.89,30.15 51.91,30.15 51.78,30.27 51.78,31.13 v1(50.6,32.31)
DDR3_DQ9: length 30.6
  TOP w0.14: U10.C7 v1(61.09,33.28) ; U12.L16 v1(47.4,33.11)
  L03_SIG1 w0.107: v1(61.09,33.28) 61.09,33.98 61.19,34.08 63.42,34.08 63.53,34.19 63.53,35.05 63.42,35.16 62.43,35.16 62.32,35.05 62.32,34.59 62.2,34.46 60.04,34.46 59.87,34.29 59.87,32.96 59.76,32.86 59.21,32.86 59.11,32.96 59.11,33.98 59,34.08 58.77,34.08 58.57,33.88 58.57,32.49 58.46,32.38 58.11,32.38 58.01,32.49 58.01,33.21 57.9,33.32 56.23,33.32 55.97,33.07 54.83,33.07 54,33.9 52.41,33.9 51.33,34.97 50.75,34.97 50.64,35.08 50.64,35.79 50.53,35.89 49.64,35.89 49.42,35.67 49.42,35.36 49.16,35.09 48.84,35.09 48.62,34.87 48.62,34.57 48.39,34.33 47.72,34.33 47.4,34.01 v1(47.4,33.11)
DDR3_DQ10: length 31.1
  TOP w0.14: U10.C2 v1(65.89,33.28) ; U12.R16 v1(48.2,29.91)
  L03_SIG1 w0.107: v1(48.2,29.91) 48.61,29.51 48.61,27.37 49.68,26.3 64.95,26.3 65.37,26.72 65.37,28.43 65.61,28.67 66.31,28.67 66.64,29 66.64,30.78 67.6,31.74 67.6,33.13 67.03,33.7 66.31,33.7 v1(65.89,33.28)
DDR3_DQ11: length 30.7
  TOP w0.14: U12.N17 v1(49,31.51) ; U10.C8 v1(60.29,33.28)
  L03_SIG1 w0.107: v1(49,31.51) 48.62,31.13 48.04,31.13 47.82,31.36 47.82,33.7 48.07,33.96 48.46,33.96 48.76,34.25 49.1,34.25 49.42,34.57 49.42,34.87 49.64,35.09 50.13,35.09 50.26,34.97 50.26,34.72 50.4,34.58 51.27,34.58 52.28,33.57 53.56,33.57 54.45,32.69 57.24,32.69 57.87,32.06 63.35,32.06 63.47,32.18 63.47,33.66 63.36,33.76 62.64,33.76 62.53,33.66 62.53,32.79 62.42,32.69 62.21,32.69 62.1,32.79 62.1,33.6 62,33.7 61.67,33.7 61.56,33.6 61.56,32.67 61.46,32.56 60.8,32.56 60.67,32.69 60.67,32.89 v1(60.29,33.28)
DDR3_DQ12: length 30.7
  TOP w0.14: U10.E3 v1(64.29,34.88) ; U12.M20 v1(51.4,32.31)
  L03_SIG1 w0.107: v1(51.4,32.31) 51.75,32.31 52.09,31.98 52.09,31.28 52.1,31.27 52.1,30.58 52.21,30.47 55.36,30.47 55.47,30.36 55.47,29.51 55.55,29.43 56.35,29.43 56.46,29.53 56.46,30.48 56.56,30.59 56.78,30.59 56.88,30.48 56.88,29.53 56.99,29.43 57.51,29.43 57.62,29.53 57.62,30.73 57.73,30.84 58.41,30.84 58.51,30.73 58.51,29.55 58.64,29.43 60.72,29.43 61.5,30.21 62.75,30.21 62.86,30.32 62.86,31.12 62.97,31.22 63.18,31.22 63.29,31.12 63.29,30.32 63.39,30.21 63.62,30.21 63.72,30.32 63.72,31.29 64.17,31.74 64.17,34.21 64.42,34.46 65.39,34.46 65.5,34.57 65.5,35.35 65.27,35.58 64.99,35.58 v1(64.29,34.88)
DDR3_DQ13: length 31.1
  TOP w0.14: U12.N18 v1(49.8,31.51) ; U10.E8 v1(60.29,34.88)
  L03_SIG1 w0.107: v1(60.29,34.88) 61.09,34.88 61.69,35.48 63.74,35.48 63.85,35.37 63.85,31.92 63.47,31.54 62.43,31.54 62.32,31.44 62.32,30.76 62.22,30.65 61.75,30.65 61.65,30.76 61.65,31.18 61.54,31.29 60.27,31.29 60.17,31.18 60.17,30.25 60.06,30.15 59.69,30.15 59.59,30.25 59.59,31.06 59.48,31.16 58.32,31.16 58.2,31.29 58.2,31.61 58.07,31.73 57.5,31.73 57.37,31.61 57.37,31.03 57.24,30.91 53.03,30.91 52.93,31.01 52.93,32.2 52.82,32.3 52.21,32.3 51.02,33.5 49.64,33.5 49.42,33.27 49.42,31.9 v1(49.8,31.51)
DDR3_DQ14: length 31.1
  TOP w0.14: U10.D2 v1(65.89,34.08) ; U12.L18 v1(49.8,33.11)
  L03_SIG1 w0.107: v1(65.89,34.08) 65.61,34.08 65.5,33.97 65.5,33.07 65.71,32.86 67.17,32.86 67.28,32.75 67.28,32.2 67.17,32.1 66.43,32.1 66.31,31.97 66.31,29.3 66.13,29.13 64.36,29.13 63.98,29.51 61.82,29.51 61.04,28.73 52.69,28.73 52.55,28.88 52.55,29.28 52.44,29.38 52.14,29.38 52.04,29.28 52.04,28.47 51.93,28.37 51.15,28.37 50.98,28.53 50.98,31.33 50.22,32.09 50.22,32.7 v1(49.8,33.11)
DDR3_DQ15: length 30.7
  TOP w0.14: v1(62.83,28.75) 62.83,34.97 62.53,35.28 U10.E7 ; U12.M18 v1(49.8,32.31)
  L03_SIG1 w0.107: v1(49.8,32.31) 49.8,32.06 50.22,31.64 50.22,28.64 50.84,28.02 51.66,28.02 51.87,27.81 55.67,27.81 56.27,28.41 59.47,28.41 59.62,28.26 59.62,27.22 59.73,27.11 59.94,27.11 60.05,27.22 60.05,28.26 60.16,28.37 60.37,28.37 60.48,28.26 60.48,27.22 60.58,27.11 60.8,27.11 60.9,27.22 60.9,28.26 61.01,28.37 61.52,28.37 61.63,28.47 61.63,28.81 62,29.19 62.67,29.19 62.83,29.02 v1(62.83,28.75)
DDR3_DQS0: length 36.8
  TOP w0.102: U12.T19 v1(50.6,29.11) ; U11.C3 v1(76.9,33.28)
  L08_SIG2 w0.089: v1(76.9,33.28) 76.64,33.54 76.16,33.54 72.29,29.67 71.46,29.67 71.37,29.58 71.37,29.01 71.11,28.75 70.69,28.75 70.43,29.01 70.43,29.58 70.34,29.67 69.99,29.67 69.9,29.58 69.9,28.07 69.47,27.64 63.12,27.64 62.69,27.21 57.77,27.21 57.24,27.73 55.63,27.73 54.83,26.93 52.71,26.93 52.29,27.35 52.29,29.61 52.17,29.73 51.4,29.73 51.03,29.36 51.03,28.71 50.94,28.62 50.69,28.62 50.6,28.71 v1(50.6,29.11)
DDR3_DQS0N: length 36.8
  TOP w0.102: U11.D3 v1(76.9,34.08) ; U12.R18 v1(49.8,29.91)
  L08_SIG2 w0.089: v1(49.8,29.91) 49.8,29.72 49.97,29.54 50.62,29.54 50.8,29.54 51.28,30.02 52.29,30.02 52.58,29.73 52.58,27.47 52.83,27.22 54.7,27.22 55.51,28.03 57.37,28.03 57.89,27.5 62.57,27.5 63,27.93 69.35,27.93 69.61,28.19 69.61,29.7 69.87,29.96 70.47,29.96 70.73,29.7 70.73,29.13 70.81,29.04 70.99,29.04 71.08,29.13 71.08,29.7 71.34,29.96 72.17,29.96 76.04,33.83 76.65,33.83 v1(76.9,34.08)
DDR3_DQS1: length 31.2
  TOP w0.102: U12.N16 v1(48.2,31.51) ; v1(55.91,32.18) 55.95,32.13 55.95,31.04 56.99,30 56.99,28.23 57.89,27.33 63.08,27.33 63.75,28 63.75,33.6 64.08,33.94 64.43,33.94 U10.C3
  L03_SIG1 w0.089: v1(48.2,31.51) 48.61,31.92 48.61,32.53 48.24,32.89 48.24,33.29 48.89,33.94 49.23,33.94 49.54,34.25 51.14,34.25 52.2,33.19 53.18,33.19 54.2,32.18 54.2,31.96 54.61,31.54 55.82,31.54 55.91,31.64 v1(55.91,32.18)
DDR3_DQS1N: length 31.2
  TOP w0.102: U12.M17 v1(49,32.31) ; U10.D3 64.43,34.22 63.97,34.22 63.47,33.72 63.47,28.11 62.96,27.61 58.01,27.61 57.27,28.34 57.27,30.12 56.23,31.16 56.23,31.64 56.36,31.76 56.36,32.3 56.54,32.49 56.68,32.49 56.86,32.3 v1(56.86,32.18)
  L03_SIG1 w0.089: v1(56.86,32.18) 56.48,32.18 56.36,32.05 56.36,31.92 56.2,31.77 56.2,31.52 55.94,31.25 54.49,31.25 53.9,31.84 53.9,32.06 53.06,32.9 52.08,32.9 51.02,33.96 49.66,33.96 49.35,33.65 49.01,33.65 48.53,33.17 48.53,33.02 48.99,32.56 48.99,32.33 v1(49,32.31)
DDR3_ODT: length 45.7
  TOP w0.14: v1(78.96,37) 78.22,37 U11.G1 ; U10.G1 66.88,36.88 v1(67.28,36.48) ; U12.T16 v1(48.2,29.11)
  L08_SIG2 w0.107: v1(78.96,37) 79.22,36.75 79.22,36.11 79.09,35.99 78.58,35.99 78.07,36.5 71.72,36.5 71.34,36.11 67.64,36.11 v1(67.28,36.48) 66.86,36.06 65.3,36.06 65.12,36.24 64.1,36.24 63.85,35.99 63.85,35.73 61.81,33.7 57.51,33.7 56.05,35.15 55.65,35.15 55.28,34.79 55.28,34.28 54.83,33.83 54.83,32.81 54.32,32.3 52.29,32.3 51.91,31.92 49.62,31.92 49.42,31.72 49.42,28.99 49.16,28.73 48.58,28.73 v1(48.2,29.11)
  BOTTOM w0.14: RA10.8 81.43,36.86 81.29,37 v1(78.96,37)
DDR3_RASN: length 49.5
  TOP w0.14: U10.F3 v1(64.29,35.68) ; v1(55.85,34.72) 57.49,34.72 57.63,34.86 57.63,35.09 57.49,35.23 56.23,35.23 55.85,35.61 55.85,36.37 55.3,36.92 53.98,36.92 52.98,35.91 U12.H20 ; U11.F3 v1(76.1,35.68)
  L08_SIG2 w0.107: v1(76.1,35.68) 76.55,35.22 76.55,34.82 76.44,34.72 76.15,34.72 76.04,34.82 76.04,35.1 75.66,35.48 75.66,35.99 75.53,36.11 71.91,36.11 71.56,35.77 67.09,35.77 67,35.68 v1(64.29,35.68) 64.74,35.22 64.74,34.57 64.84,34.46 66.13,34.46 66.31,34.29 66.31,33.86 66.13,33.69 65,33.69 64.74,33.96 63.04,33.96 61.94,32.86 55.42,32.86 55.29,32.99 55.29,33.78 55.85,34.34 v1(55.85,34.72)
  BOTTOM w0.14: RA10.5 80.87,35.36 80.57,35.66 77.55,35.66 77.06,36.15 76.57,36.15 v1(76.1,35.68)
DDR3_RSTN: length 42.5
  TOP w0.14: 77.3,42.59 78.71,44 R69.2 ; 77.3,42.59 U11.N2 ; 77.3,42.59 76.92,42.97 65.98,42.97 v1(65.09,42.08) U10.N2 ; U12.H18 v1(49.8,36.31)
  BOTTOM w0.14: v1(49.8,36.31) 49.82,36.31 50.26,36.75 51.15,36.75 51.53,37.13 51.53,39.67 54.7,42.85 64.32,42.85 v1(65.09,42.08) 65.62,42.08 66.01,42.46 66.01,44.75 TP13.1
DDR3_VDD: length 45.2
  TOP w0.33: C74.2 v1(80.87,41.96)
  TOP w0.356: U11.K9 v1(71.3,39.68) ; U10.M9 v1(59.49,41.28) ; U10.B9 v1(59.49,32.48) ; U10.A9 v1(59.49,31.68) ; U11.M9 v1(71.3,41.28) ; U10.G8 v1(60.29,37.28) ; U11.K1 79.46,39.28 80.13,39.95 C75.2 81.15,39.95 v1(81.53,40.33) ; U11.G8 v1(72.1,37.28) ; U11.B9 v1(71.3,32.48) ; U10.M1 66.73,41.32 v1(67.15,41.32) ; C74.2 79.24,41.35 78.77,40.88 U11.M1 ; U10.K1 v1(66.69,39.68) ; U10.C1 v1(66.69,33.28) ; U10.G2 v1(65.89,37.28) ; U10.D7 v1(61.89,34.88) ; U11.E9 v1(71.3,34.88) ; U11.G2 v1(77.7,37.28) ; U10.A2 v1(65.89,31.68) ; U11.A2 v1(77.7,31.68) ; U10.K9 v1(59.49,39.68) ; U11.A9 v1(71.3,31.68) ; U11.E2 v1(77.7,34.88) ; U10.E9 v1(59.49,34.88) ; U10.E2 v1(65.89,34.88) ; U11.D7 v1(73.7,34.88) ; U11.C1 v1(78.5,33.28)
  BOTTOM w0.356: C128.2 59.34,41.42 v1(59.49,41.28) ; C138.2 67.3,39.68 v1(66.69,39.68) ; C184.2 79.01,33.28 v1(78.5,33.28) ; v1(65.37,30.04) C198.1 C193.1 ; v1(59.49,39.68) 58.86,39.68 C135.1 ; v1(77.7,34.88) 77.11,34.88 C161.2 ; C152.1 66.4,37.28 v1(65.89,37.28) ; v1(71.3,39.68) 70.8,39.68 C134.2 ; C192.2 71.57,30.91 71.3,31.19 v1(71.3,31.68) ; v1(71.3,32.48) 71.15,32.62 C185.2 ; C129.1 71.23,41.34 v1(71.3,41.28) ; C193.1 65.98,31.58 v1(65.89,31.68) ; C193.1 v1(65.37,30.91) ; v1(77.7,37.28) 77.46,37.51 77.44,37.51 77.06,37.89 C146.2 ; C178.1 67.03,33.28 v1(66.69,33.28) ; C189.1 77.7,31.21 v1(77.7,31.68) ; v1(73.7,34.88) 73.7,34.39 C168.2 ; C169.2 61.89,34.38 v1(61.89,34.88) ; C165.1 59.35,34.74 v1(59.49,34.88) ; C130.1 67.56,41.32 v1(67.15,41.32) ; v1(71.3,34.88) 71.16,34.74 C164.2 ; v1(65.89,34.88) 65.45,34.88 65.12,34.55 C170.2 ; C155.1 60.29,37.16 60.29,37.19 60.29,37.2 v1(60.29,37.28) ; v1(72.1,37.28) 72.35,37.03 72.35,36.52 C154.1 ; C186.1 59.43,32.53 v1(59.49,32.48) v1(59.49,31.68) 59.49,31.31 59.63,31.16 C190.1 C197.1
  BOTTOM w0.381: C197.1 v1(59.05,30.17)
  vias: v1(67.66,29.13) v1(69.18,29.13) v1(70.58,28.24) v1(78.45,29) v1(78.45,27.86) v1(79.47,29) v1(79.47,27.86) v1(80.49,29) v1(80.49,27.86) v1(81.63,29) v1(81.63,27.86)
DDR3_VREF: length 2
  BOTTOM w0.254: C132.2 91.41,39.64 91.59,39.45 91.96,39.45 92.31,39.1 U19.6
DDR3_VTT: length 2.4
  BOTTOM w0.254: U19.3 93.31,35.35 92.8,34.84 92.8,34.4
  BOTTOM w0.279: U19.5 92.31,35.12
DDR3_WEN: length 49.2
  TOP w0.14: U10.H3 64.6,37.77 v1(63.98,37.77) ; U12.K20 v1(53.67,34.31) ; U11.H3 v1(76.1,37.28)
  L08_SIG2 w0.107: v1(53.67,34.31) 53.41,34.31 53.18,34.08 53.18,32.92 53.29,32.81 54.22,32.81 54.51,33.11 54.51,34.01 54.96,34.46 54.96,35.99 55.28,36.3 57.23,36.3 57.42,36.11 57.42,34.7 57.53,34.59 57.74,34.59 57.85,34.7 57.85,36.39 57.95,36.5 58.17,36.5 58.27,36.39 58.27,34.7 58.38,34.59 58.59,34.59 58.7,34.7 58.7,36.39 58.81,36.5 60.17,36.5 60.57,36.1 61.46,36.1 61.82,35.73 62.58,35.73 62.83,35.99 62.83,37.15 62.94,37.26 63.87,37.26 63.98,37.36 v1(63.98,37.77) 65.43,37.77 65.5,37.7 66.1,37.7 66.28,37.52 68.81,37.52 69.05,37.76 69.05,37.91 69.16,38.02 69.4,38.02 69.51,37.91 69.51,37.24 69.61,37.13 69.83,37.13 69.93,37.24 69.93,37.91 70.04,38.02 71.6,38.02 71.96,37.66 73.88,37.66 74.26,37.28 v1(76.1,37.28)
  BOTTOM w0.14: 82.02,35.86 81.24,35.86 81.03,36.08 77.64,36.08 77.09,36.62 76.75,36.62 v1(76.1,37.28)
DDR_1V35: length 24.6
  TOP w0.381: R10.1 v1(34.07,90.92) ; C5.1 v1(34.07,92.06)
  L05_PWR1 w0.381: v1(34.07,92.06) v1(34.07,90.92) 33.37,90.22 v1(33.37,69.26)
DDR_FULL_LED7: length 80.1
  TOP w0.14: U12.E10 v1(42.6,38.71) ; LD6.1 v1(10.38,93.65)
  L03_SIG1 w0.107: v1(42.6,38.71) 43.05,39.16 43.15,39.16 43.78,39.8 43.78,42.04 44.4,42.66 44.4,58.96 44.98,59.54 44.98,73.27 43.02,75.23 28.67,75.23 10.38,93.52 v1(10.38,93.65)
DMM_CLK: length 23.4
  TOP w0.14: R94.2 31.21,34.68 v1(31.21,33.83) ; J3.15 23.96,32.04 v1(23.97,32.05)
  L03_SIG1 w0.107: v1(31.21,33.83) 31.21,39.16 30.6,39.77 24.71,39.77 23.97,39.04 v1(23.97,32.05)
DMM_CLK_C: length 5.7
  TOP w0.14: U12.G1 35.21,36.71 34.92,37 32.61,37 31.97,36.37 31.1,36.37 30.96,36.23 R94.1
DMM_MUX_CTL: length 15.9
  TOP w0.14: v1(14.46,32.18) 14.58,32.06 15.66,32.06 J3.16
  L08_SIG2 w0.107: v1(26.26,27.48) 25.11,28.62 22.95,28.62 19.4,32.18 v1(14.46,32.18)
  BOTTOM w0.14: v1(26.26,27.48) R120.2
DMM_MUX_CTL_C: length 13.1
  TOP w0.14: U12.P5 v1(38.6,30.71)
  L08_SIG2 w0.107: v1(38.6,30.71) 35.21,30.71 34.89,30.4 34.89,29.64 33.24,27.99 30.07,27.99 v1(29.43,27.35)
  BOTTOM w0.14: v1(29.43,27.35) 28.8,27.35 28.67,27.48 R120.1
DMM_SYNC: length 24
  TOP w0.14: J3.17 22.88,31.54 22.89,31.54 v1(23.21,31.54) ; R95.2 32.57,34.93 v1(32.86,35.23)
  L03_SIG1 w0.107: v1(23.21,31.54) 23.21,38.78 24.61,40.18 30.83,40.18 31.59,39.42 31.59,35.61 31.97,35.23 v1(32.86,35.23)
DMM_SYNC_C: length 5
  TOP w0.14: U12.H2 36.2,36.32 34.82,36.32 34.64,36.5 32.82,36.5 R95.1
DONE: length 60.5
  TOP w0.14: TP2.1 83.03,26.51 R107.2 R104.2 ; U12.Y3 v1(37,25.91)
  L08_SIG2 w0.107: v1(37,25.91) 37,23.97 38.96,22.02 49.88,22.02 50.01,21.89 65.15,21.89 67.31,19.73 80.39,19.73 82.39,21.73 82.39,25.32 82.7,25.62 TP2.1
DP0: length 23.1
  TOP w0.14: v1(23.97,31.03) 23.39,31.03 23.39,31.04 J3.19 ; v1(29.69,33.07) 29.82,33.07 29.83,33.07 RA1.5
  L03_SIG1 w0.107: v1(29.69,33.07) 29.69,35.35 29.18,35.86 26.34,35.86 26.23,35.75 26.23,32.16 26.12,32.05 25.75,32.05 25.62,32.18 25.62,35.75 25.52,35.86 25.24,35.86 25.11,35.73 25.11,31.16 24.99,31.03 v1(23.97,31.03)
DP0_C: length 5.7
  TOP w0.14: RA1.4 31.59,33.07 32.99,34.46 33.3,34.46 34.48,35.64 35.53,35.64 U12.H1
DP1: length 23.1
  TOP w0.14: v1(23.21,30.53) 22.95,30.53 22.95,30.54 J3.21 ; RA1.6 29.94,32.43 v1(29.43,31.92)
  L03_SIG1 w0.107: v1(29.43,31.92) 28.8,31.92 28.54,32.18 28.54,35.35 28.42,35.48 27.15,35.48 27.02,35.35 27.02,30.78 26.76,30.53 26.1,30.53 25.99,30.42 25.99,28.92 25.88,28.82 25.67,28.82 25.56,28.92 25.56,30.42 25.46,30.53 25.24,30.53 25.14,30.42 25.14,28.92 25.03,28.82 24.82,28.82 24.71,28.92 24.71,30.42 24.6,30.53 v1(23.21,30.53)
DP1_C: length 5.6
  TOP w0.14: RA1.3 31.41,32.43 31.41,32.43 31.59,32.43 33.11,33.96 33.62,33.96 34.78,35.11 U12.J1
DP2: length 23.4
  TOP w0.14: J3.23 22.81,30.04 v1(23.21,29.64) ; v1(29.18,31.16) 29.63,31.16 29.81,31.35 29.81,31.67 30.07,31.92 30.19,31.92 30.2,31.93 RA1.7
  L03_SIG1 w0.107: v1(23.21,29.64) 22.68,29.64 22.45,29.87 22.45,33.71 22.33,33.83 21.93,33.83 21.81,33.71 21.81,28.88 22.19,28.49 27.27,28.49 27.65,28.88 27.65,31.06 27.76,31.16 v1(29.18,31.16)
DP2_C: length 5.7
  TOP w0.14: RA1.2 31.78,31.93 33.3,33.45 33.75,33.45 34.89,34.59 35.53,34.59 U12.K1
DP3: length 21.7
  TOP w0.14: J3.25 v1(20.67,29.54) ; v1(29.56,30.53) 29.62,30.53 RA1.8
  L03_SIG1 w0.107: v1(29.56,30.53) 29.56,29.38 29.43,29.26 28.54,29.26 27.4,28.11 22.57,28.11 22.19,27.73 22.19,24.3 22.08,24.19 21.42,24.19 21.3,24.3 21.3,29.38 21.15,29.54 v1(20.67,29.54)
DP3_C: length 6.6
  TOP w0.14: U12.K2 36.21,33.92 35.11,33.92 34.13,32.94 33.43,32.94 31.78,31.29 RA1.1
DP4: length 17.4
  TOP w0.14: RA2.5 28.3,29.89 28.03,30.16 28.03,31.36 27.9,31.5 27.54,31.5 27.4,31.36 27.4,29.9 27.26,29.76 26.9,29.76 26.76,29.9 26.76,33.18 26.63,33.32 25.37,33.32 25.11,33.07 25.11,29.51 24.73,29.13 22.57,29.13 22.48,29.04 J3.27
DP4_C: length 11.4
  TOP w0.14: RA2.4 30.01,30.21 30.45,30.65 30.96,30.65 31.59,30.02 32.23,30.02 32.48,30.27 v1(32.48,31.29) ; U12.K3 v1(37,34.71)
  L03_SIG1 w0.107: v1(37,34.71) 36.8,34.71 36.8,34.72 35.02,34.72 32.48,32.18 v1(32.48,31.29)
DP5: length 14.2
  TOP w0.14: J3.29 22.62,28.54 22.7,28.62 25.24,28.62 25.62,29 25.62,32.55 25.76,32.69 26.12,32.69 26.26,32.55 26.26,29.51 26.51,29.25 RA2.6
DP5_C: length 14.5
  TOP w0.14: v1(30.7,30.15) 30.7,29.64 30.32,29.26 30.31,29.26 30.31,29.25 RA2.3 ; U12.K4 v1(37.8,34.71)
  L03_SIG1 w0.107: v1(37.8,34.71) 38.19,35.11 38.19,35.86 37.81,36.24 35.02,36.24 30.7,31.92 v1(30.7,30.15)
DP6: length 12.3
  TOP w0.14: 29.11,28.75 26.28,28.75 26.13,28.61 26.13,28.11 26.26,27.99 26.76,27.99 26.89,27.86 26.89,26.6 26.75,26.46 25.51,26.46 25.37,26.6 25.37,27.97 25.23,28.11 22.83,28.11 22.75,28.04 J3.31
DP6_C: length 16.5
  TOP w0.14: v1(30.7,28.75) 30.57,28.75 30.57,28.75 30.01,28.75 ; U12.J5 v1(38.6,35.51)
  L03_SIG1 w0.107: v1(38.6,35.51) 38.6,36.09 38.07,36.62 34,36.62 33.5,36.11 33.5,35.23 30.19,31.92 30.19,28.88 30.32,28.75 v1(30.7,28.75)
DP7: length 15
  TOP w0.14: v1(28.29,28.24) 28.98,28.24 RA2.8 ; J3.33 22.89,27.54 22.95,27.61 v1(23.84,27.61)
  L03_SIG1 w0.107: v1(23.84,27.61) 24.48,26.97 24.99,26.97 25.37,26.59 25.37,25.3 25.47,25.19 27.91,25.19 28.03,25.32 28.03,26.97 28.92,27.86 29.69,27.86 29.81,27.99 29.81,28.49 29.69,28.62 28.67,28.62 v1(28.29,28.24)
DP7_C: length 13.6
  TOP w0.14: U12.K5 v1(38.6,34.71) ; v1(33.11,31.8) 33.11,29.38 31.85,28.12 RA2.1
  L03_SIG1 w0.107: v1(33.11,31.8) 33.62,32.3 33.62,32.81 35.02,34.21 38.1,34.21 v1(38.6,34.71)
DP8: length 14.2
  TOP w0.14: RA3.5 29.68,26.72 v1(29.56,26.59) ; J3.35 23.15,27.04 v1(23.21,27.1)
  L03_SIG1 w0.107: v1(23.21,27.1) 22.7,26.59 22.7,24.43 22.95,24.18 29.18,24.18 29.56,24.56 v1(29.56,26.59)
DP8_C: length 14.3
  TOP w0.14: RA3.4 31.83,26.72 31.97,26.86 v1(31.97,27.35) ; U12.J4 v1(37.8,35.51)
  L03_SIG1 w0.107: v1(31.97,27.35) 31.97,30.02 31.54,30.45 31.54,31.74 34.89,35.1 37.39,35.1 v1(37.8,35.51)
DP9: length 14.3
  TOP w0.14: v1(28.54,26.08) 28.99,26.08 29,26.08 RA3.6 ; v1(23.97,26.59) 23.92,26.54 J3.37
  L03_SIG1 w0.107: v1(28.54,26.08) 29.05,26.08 29.18,25.95 29.18,24.68 29.05,24.56 23.34,24.56 23.22,24.67 23.22,26.22 23.59,26.59 v1(23.97,26.59)
DP9_C: length 14.2
  TOP w0.14: RA3.3 31.97,26.08 v1(32.29,26.4) ; U12.L5 v1(38.6,33.11)
  L03_SIG1 w0.107: v1(38.6,33.11) 37.91,33.81 35.13,33.81 34,32.69 34,32 32.41,30.4 32.41,26.52 v1(32.29,26.4)
DP10: length 13.6
  TOP w0.14: RA3.7 30.25,25.57 29.83,25.57 29.69,25.43 29.69,24.44 29.55,24.3 29.17,24.3 29.03,24.44 29.03,25.43 28.89,25.57 28.29,25.57 28.03,25.83 28.03,27.36 27.9,27.5 27.56,27.5 27.4,27.34 27.4,26.22 27.13,25.95 24.48,25.95 24.4,26.04 J3.39
DP10_C: length 15.5
  TOP w0.14: U12.J3 v1(37,35.51) ; v1(31.84,25.57) 31.84,25.58 RA3.2
  L03_SIG1 w0.107: v1(37,35.51) 36.62,35.89 35.18,35.89 31.21,31.92 31.21,31.29 31.22,31.28 31.22,30.27 31.54,29.95 31.54,25.88 v1(31.84,25.57)
DP11: length 15.7
  TOP w0.14: RA3.8 30.25,23.94 30.11,23.8 28.68,23.8 28.54,23.94 28.54,24.67 28.4,24.81 27.91,24.81 27.78,24.68 27.78,22.28 27.64,22.14 27.27,22.14 27.15,22.27 27.15,24.81 26.51,25.45 24.35,25.45 24.26,25.54 J3.41
DP11_C: length 13.2
  TOP w0.14: v1(32.86,25.45) 32.35,24.94 RA3.1 ; U12.M4 v1(37.8,32.31)
  L03_SIG1 w0.107: v1(37.8,32.31) 37.42,32.7 35.92,32.7 34.89,31.67 34.64,31.67 33.17,30.2 33.17,25.75 v1(32.86,25.45)
DP12: length 14.8
  TOP w0.14: J3.43 24.13,25.04 24.35,24.81 26.5,24.81 26.64,24.67 26.64,21.82 26.78,21.68 28.4,21.68 28.54,21.82 28.54,23.03 28.8,23.29 30.45,23.29 30.7,23.54 30.7,23.95 30.8,24.05 31.13,24.05 31.27,23.91 RA4.5
DP12_C: length 14.2
  TOP w0.14: RA4.4 32.17,24.16 32.31,24.3 v1(32.35,24.3) ; U12.L4 v1(37.8,33.11)
  L03_SIG1 w0.107: v1(37.8,33.11) 37.42,33.5 36.04,33.5 35.78,33.23 35.78,33.07 34.77,32.05 34.51,32.05 32.73,30.27 32.73,26.08 32.35,25.7 v1(32.35,24.3)
DP13: length 15.6
  TOP w0.14: RA4.6 30.7,22.9 30.57,22.78 30.33,22.78 30.19,22.64 30.19,21.7 30.05,21.56 29.72,21.56 29.58,21.7 29.58,22.64 29.44,22.78 29.16,22.78 29.02,22.64 29.02,21.4 28.88,21.26 26.51,21.26 26.13,21.64 26.13,23.92 25.75,24.3 24.22,24.3 23.99,24.54 J3.45
DP13_C: length 13.3
  TOP w0.14: v1(33.88,23.8) 33.37,23.8 32.48,22.9 RA4.3 ; U12.N4 v1(37.8,31.51)
  L03_SIG1 w0.107: v1(33.88,23.8) 33.88,29.89 34.89,30.91 37.2,30.91 v1(37.8,31.51)
DP14: length 13.9
  TOP w0.14: RA4.7 31.26,22.4 30.96,22.4 30.7,22.14 30.7,20.82 30.56,20.68 30.22,20.68 29.77,21.13 29.43,21.13 29.05,20.75 26.26,20.75 25.62,21.38 25.62,23.66 25.48,23.8 24.1,23.8 23.86,24.04 J3.47
DP14_C: length 14.5
  TOP w0.14: RA4.2 32.74,22.4 v1(33.5,23.16) ; U12.N5 v1(38.6,31.51)
  L03_SIG1 w0.107: v1(33.5,23.16) 34.13,23.16 34.38,23.41 34.38,27.48 34.83,27.92 34.83,30.21 35.15,30.53 37.61,30.53 v1(38.6,31.51)
DP15: length 13.2
  TOP w0.14: RA4.8 31.27,20.55 30.96,20.24 26.13,20.24 25.11,21.26 25.11,23.16 24.99,23.29 23.97,23.29 23.72,23.54 J3.49
DP15_C: length 15.8
  TOP w0.14: v1(32.99,22.02) 32.74,21.77 RA4.1 ; U12.M5 v1(38.6,32.31)
  L03_SIG1 w0.107: v1(38.6,32.31) 38.21,31.92 36.42,31.92 35.78,31.29 34.77,31.29 33.5,30.02 33.5,24.3 32.99,23.8 v1(32.99,22.02)
ECP5U_VREF: length 0.6
  TOP w0.356: U12.P16 v1(48.2,30.71)
  vias: v1(51.66,24.81) v1(52.55,24.81) v1(91.79,45.13) v1(91.79,44.24)
EEPROM_ADD: length 41.4
  TOP w0.14: v1(27.78,57.32) R50.2 U7.3 ; U12.E12 v1(45,38.71)
  BOTTOM w0.14: v1(27.78,57.32) 28.16,56.94 41.5,56.94 47.85,50.59 47.85,43.48 47,42.63 47,39.33 46.7,39.04 46.05,39.04 45.97,39.12 45.4,39.12 v1(45,38.71)
EEPROM_RD_FAIL_LED6: length 76
  TOP w0.14: LD9.1 v1(19.27,93.65) ; U12.C11 v1(44.2,40.31)
  L03_SIG1 w0.107: v1(44.2,40.31) 44.2,40.34 44.93,41.07 44.93,41.58 45.89,42.55 45.89,56.76 47.34,58.21 47.34,74.85 43.4,78.79 29.18,78.79 20.67,87.3 20.67,92.25 v1(19.27,93.65)
EEPROM_WP: length 25.3
  TOP w0.14: U12.A12 44.6,42.58 44.34,42.85 43.53,42.85 43.27,43.11 43.27,48.84 38.97,53.13 34.51,53.13 34.12,53.52 34.12,56.56 34.25,56.69 U7.7 R49.1
ETH_D0N: length 20.9
  TOP w0.102: v1(76.63,52.9) 76.27,53.26 76.27,53.38 75.98,53.67 73.09,53.67 72.87,53.89 72.87,56.58 72.48,56.96 72.09,56.96 71.97,57.07 U6.3
  BOTTOM w0.102: v1(76.63,52.9) 76.32,53.21 76.32,53.65 76.82,54.15 78.08,54.15 U18.6 U18.5 79.08,54.15 79.46,54.15 79.57,54.03 79.57,52.38 81.36,50.59 82.9,50.59 83.74,51.44 83.89,51.44 J6.10
ETH_D0P: length 21
  TOP w0.102: v1(75.74,52.9) 75.99,53.16 75.99,53.26 75.87,53.39 72.98,53.39 72.59,53.78 72.59,56.46 72.36,56.68 72.1,56.68 71.99,56.57 U6.2
  BOTTOM w0.102: J6.9 83.18,51.99 83.41,51.76 83.41,51.61 82.67,50.87 81.48,50.87 79.85,52.5 79.85,54.15 79.57,54.43 79.08,54.43 U18.4 U18.7 78.09,54.43 76.7,54.43 76.04,53.77 76.04,53.21 v1(75.74,52.9)
ETH_D1N: length 21
  TOP w0.102: U6.6 71.87,58.57 71.99,58.45 72.88,58.45 73.63,57.7 75.93,57.7 76.24,57.39 76.24,56.87 76.55,56.56 77.43,56.56 77.69,56.3 77.69,55.68 77.43,55.42 76.93,55.42 76.8,55.29 76.8,55.24 v1(77.11,54.94)
  BOTTOM w0.102: v1(77.11,54.94) 76.8,55.24 76.8,55.55 76.91,55.65 78.09,55.65 U18.9 U18.2 79.08,55.65 80.12,55.65 80.46,55.3 80.46,53.4 80.75,53.11 82.86,53.11 83.71,53.96 83.9,53.96 J6.8
ETH_D1P: length 21
  TOP w0.102: v1(76.22,54.94) 76.52,55.24 76.52,55.41 76.81,55.7 77.31,55.7 77.41,55.8 77.41,56.18 77.31,56.28 76.43,56.28 75.96,56.75 75.96,57.27 75.81,57.43 73.51,57.43 72.76,58.17 71.96,58.17 71.86,58.07 U6.5
  BOTTOM w0.102: v1(76.22,54.94) 76.52,55.24 76.52,55.66 76.79,55.93 78.09,55.93 U18.10 U18.1 79.08,55.93 80.23,55.93 80.74,55.42 80.74,53.51 80.87,53.39 82.75,53.39 83.32,53.96 83.32,54.26 83.05,54.53 J6.7
ETH_D2N: length 20.8
  TOP w0.102: v1(77.64,57.1) 77.34,57.4 77.34,57.6 78.45,58.72 78.45,59.36 77.18,60.63 73.12,60.63 72.78,60.96 72.15,60.96 72.04,61.07 U6.11
  BOTTOM w0.102: J6.6 83.9,56.5 83.73,56.5 83,55.77 81.13,55.77 80.59,56.32 80.59,57.6 80.36,57.83 79.08,57.83 U17.5 U17.6 77.76,57.72 77.65,57.83 77.44,57.83 77.34,57.73 77.34,57.4 v1(77.64,57.1)
ETH_D2P: length 20.8
  TOP w0.102: v1(76.75,57.1) 77.06,57.4 77.06,57.72 78.17,58.84 78.17,59.24 77.07,60.35 73,60.35 72.67,60.68 72.16,60.68 72.05,60.57 U6.10
  BOTTOM w0.102: J6.5 83.05,57.07 83.39,56.73 83.39,56.56 82.88,56.05 81.25,56.05 80.87,56.43 80.87,57.72 80.48,58.11 79.08,58.11 U17.4 U17.7 77.76,58.22 77.65,58.11 77.32,58.11 77.06,57.85 77.06,57.4 v1(76.75,57.1)
